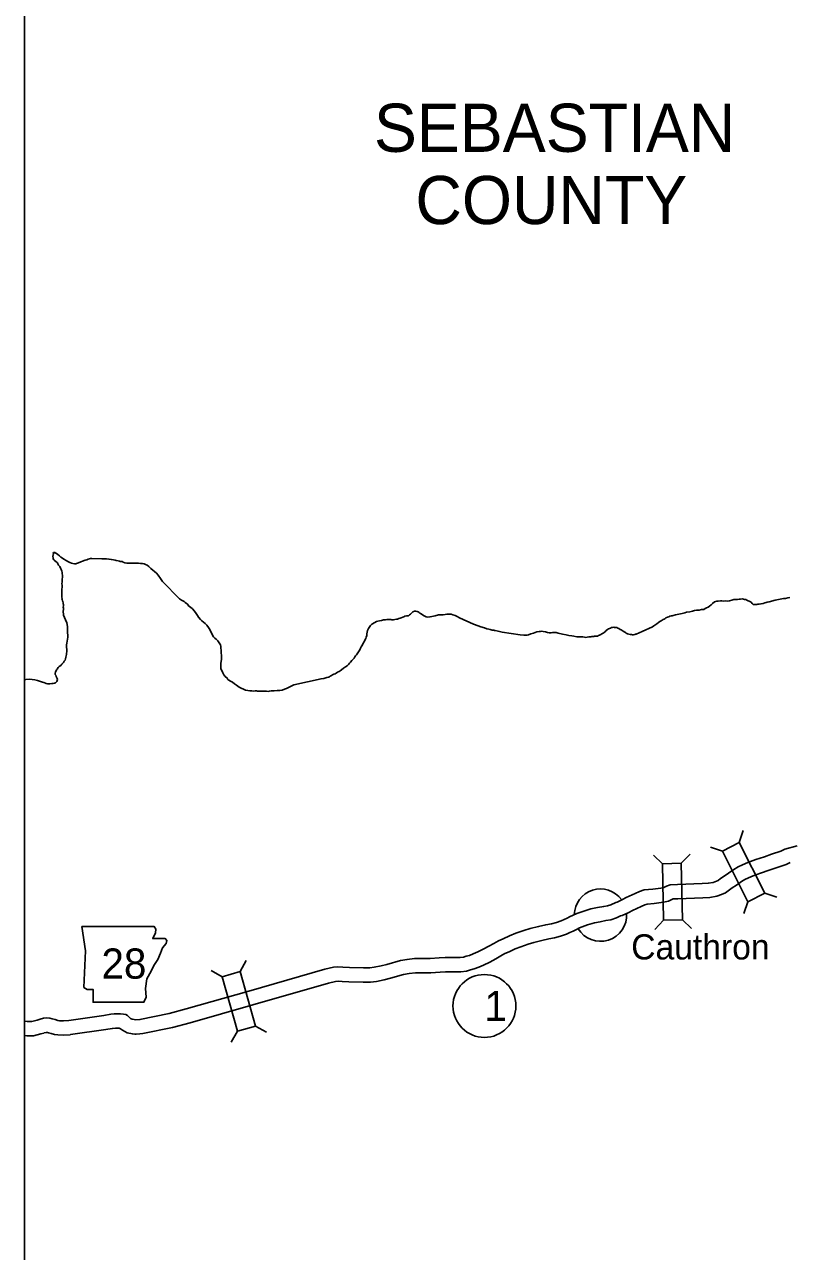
# Model space of a CAD drawing. Extents: x 1382482 to 1385815, y 1168351 to 1170484.
# Drawn here: x 1382642.2 to 1382802.8, y 1169997.3 to 1170254.7 of the extents above; entities that cross this region are included whole.
import ezdxf

# ---------------------------------------------------------------- set-up
doc = ezdxf.new("R2010")
doc.units = 0
for name, color, linetype in [('10', 7, 'Continuous'), ('2', 7, 'Continuous'), ('20', 7, 'Continuous'), ('21', 7, 'Continuous'), ('24', 7, 'Continuous'), ('Default', 7, 'Continuous'), ('R_No Plot', 7, 'Continuous')]:
    doc.layers.add(name, color=color, linetype=linetype)

msp = doc.modelspace()

# ---------------------------------------------------------------- linework, layer by layer
at = {"layer": '10'}
for points in [[(1382804.4, 1170082.41), (1382801.83, 1170081.72), (1382800.95, 1170081.28), (1382798.98, 1170080.63), (1382797.53, 1170080.11), (1382795.74, 1170079.52), (1382794.05, 1170078.93), (1382792.91, 1170078.45), (1382792.01, 1170078), (1382791.07, 1170077.46), (1382789.99, 1170076.65), (1382789.05, 1170076.07), (1382788.33, 1170075.52), (1382787.83, 1170075.13), (1382787.43, 1170074.97), (1382786.79, 1170074.74), (1382785.72, 1170074.56), (1382784.45, 1170074.5), (1382779.26, 1170074.28), (1382777.75, 1170074.25), (1382777, 1170073.96), (1382776.38, 1170073.66), (1382775.81, 1170073.53), (1382774.07, 1170073.31), (1382772.3, 1170073.15), (1382771.28, 1170072.81), (1382770.4, 1170072.39), (1382768.51, 1170071.54), (1382767.73, 1170071.14), (1382766.64, 1170070.62), (1382766.3, 1170070.54), (1382765.3, 1170070.05), (1382764.59, 1170069.8), (1382763.79, 1170069.71), (1382762.45, 1170069.44), (1382761.1, 1170069.19), (1382759.44, 1170068.65), (1382758.18, 1170068.24), (1382757.38, 1170067.88), (1382756.63, 1170067.49), (1382756.14, 1170067.2), (1382755.48, 1170066.96), (1382754.87, 1170066.67), (1382753.88, 1170066.33), (1382752.81, 1170066.07), (1382751.64, 1170065.85), (1382750.12, 1170065.47), (1382748.37, 1170065.05), (1382747.03, 1170064.64), (1382745.34, 1170064.05), (1382743.99, 1170063.54), (1382742.69, 1170062.91), (1382741.73, 1170062.49), (1382740.73, 1170061.92), (1382739.71, 1170061.34), (1382738.52, 1170060.7), (1382737.35, 1170060.15), (1382736.4, 1170059.75), (1382735.61, 1170059.42), (1382734.95, 1170059.23), (1382734.37, 1170059.05), (1382733.65, 1170058.96), (1382730.49, 1170058.99), (1382729.22, 1170058.92), (1382727.38, 1170058.76), (1382724.09, 1170058.78), (1382722.53, 1170058.59), (1382721.11, 1170058.35), (1382718.3, 1170057.53), (1382717.07, 1170057.24), (1382715.61, 1170056.92), (1382714.67, 1170056.8), (1382713.36, 1170056.8), (1382710.42, 1170056.87), (1382709.01, 1170056.97), (1382707.95, 1170057), (1382707.05, 1170056.92), (1382705.29, 1170056.5), (1382689.34, 1170051.92), (1382676.18, 1170048.2), (1382672.6, 1170047.23), (1382666.43, 1170045.97), (1382665.61, 1170045.91)], [(1382802.89, 1170078.9), (1382802.1, 1170078.5), (1382799.96, 1170077.8), (1382798.51, 1170077.27), (1382796.71, 1170076.68), (1382795.13, 1170076.12), (1382794.16, 1170075.72), (1382793.44, 1170075.36), (1382792.72, 1170074.94), (1382791.67, 1170074.17), (1382790.75, 1170073.6), (1382790.16, 1170073.15), (1382789.36, 1170072.52), (1382788.52, 1170072.17), (1382787.55, 1170071.82), (1382786.04, 1170071.57), (1382784.58, 1170071.51), (1382779.36, 1170071.29), (1382778.34, 1170071.26), (1382778.21, 1170071.21), (1382777.39, 1170070.8), (1382776.33, 1170070.57), (1382774.4, 1170070.32), (1382772.92, 1170070.19), (1382772.39, 1170070.01), (1382771.65, 1170069.67), (1382769.81, 1170068.83), (1382769.05, 1170068.45), (1382767.65, 1170067.78), (1382767.33, 1170067.7), (1382766.47, 1170067.28), (1382765.26, 1170066.85), (1382764.25, 1170066.74), (1382763.02, 1170066.49), (1382761.84, 1170066.27), (1382760.37, 1170065.8), (1382759.27, 1170065.43), (1382758.69, 1170065.18), (1382758.07, 1170064.85), (1382757.4, 1170064.47), (1382756.65, 1170064.2), (1382756.01, 1170063.89), (1382754.73, 1170063.45), (1382753.44, 1170063.14), (1382752.28, 1170062.92), (1382750.83, 1170062.55), (1382749.15, 1170062.16), (1382747.96, 1170061.79), (1382746.36, 1170061.23), (1382745.18, 1170060.78), (1382743.94, 1170060.18), (1382743.07, 1170059.8), (1382742.21, 1170059.32), (1382741.17, 1170058.72), (1382739.87, 1170058.02), (1382738.57, 1170057.4), (1382737.55, 1170056.98), (1382736.61, 1170056.59), (1382735.82, 1170056.36), (1382734.98, 1170056.1), (1382733.81, 1170055.96), (1382730.56, 1170055.99), (1382729.44, 1170055.93), (1382727.5, 1170055.76), (1382724.26, 1170055.78), (1382722.96, 1170055.62), (1382721.78, 1170055.42), (1382719.07, 1170054.63), (1382717.74, 1170054.31), (1382716.11, 1170053.96), (1382714.86, 1170053.8), (1382713.32, 1170053.8), (1382710.28, 1170053.87), (1382708.87, 1170053.97), (1382708.04, 1170053.99), (1382707.53, 1170053.95), (1382706.05, 1170053.6), (1382690.16, 1170049.04), (1382676.98, 1170045.31), (1382673.3, 1170044.31), (1382667.09, 1170043.05)], [(1382660.33, 1170047.07), (1382658.86, 1170046.82), (1382651.5, 1170045.78)], [(1382660.33, 1170047.07), (1382661.05, 1170047.16), (1382661.68, 1170047.19), (1382662.35, 1170047.19), (1382662.97, 1170047.12), (1382663.49, 1170046.99), (1382663.83, 1170046.78), (1382664.14, 1170046.51), (1382664.49, 1170046.21), (1382664.83, 1170046.02), (1382665.27, 1170045.94), (1382665.61, 1170045.91)], [(1382645.48, 1170046.03), (1382644.85, 1170045.82), (1382643.77, 1170045.56), (1382642.79, 1170045.58), (1382642.23, 1170045.59)], [(1382645.48, 1170046.03), (1382646.19, 1170046.24), (1382646.8, 1170046.3), (1382647.51, 1170046.24), (1382648.03, 1170046.12), (1382648.65, 1170045.95), (1382649.2, 1170045.78), (1382649.59, 1170045.72), (1382650.39, 1170045.67), (1382651.5, 1170045.78)], [(1382646.26, 1170043.13), (1382645.68, 1170042.94), (1382644.1, 1170042.55), (1382642.72, 1170042.58), (1382642.23, 1170042.59)], [(1382646.32, 1170043.15), (1382646.78, 1170043.28), (1382646.82, 1170043.28), (1382647.05, 1170043.26), (1382647.29, 1170043.21), (1382647.81, 1170043.06), (1382648.53, 1170042.85), (1382649.25, 1170042.73), (1382650.44, 1170042.66), (1382651.79, 1170042.79)], [(1382660.59, 1170044.07), (1382659.32, 1170043.86), (1382651.85, 1170042.8)], [(1382660.69, 1170044.08), (1382660.59, 1170044.07)], [(1382660.69, 1170044.08), (1382661.31, 1170044.16)], [(1382661.31, 1170044.16), (1382661.73, 1170044.18), (1382662.06, 1170044.13), (1382662.37, 1170043.99), (1382662.78, 1170043.73)], [(1382662.78, 1170043.73), (1382663.78, 1170043.15), (1382664.87, 1170042.95), (1382665.35, 1170042.91)], [(1382665.35, 1170042.91), (1382665.69, 1170042.9), (1382666.41, 1170042.98), (1382667.09, 1170043.05)]]:
    msp.add_lwpolyline(points, dxfattribs=at)
at = {"layer": '2'}
for points in [[(1382647.53, 1170116.39), (1382647.95, 1170116.44), (1382648.25, 1170116.46), (1382648.52, 1170116.52), (1382648.72, 1170116.63), (1382648.88, 1170116.75), (1382648.99, 1170116.88), (1382649.08, 1170117.06), (1382649.12, 1170117.32), (1382649.09, 1170117.51), (1382648.96, 1170117.77), (1382648.88, 1170117.9), (1382648.78, 1170118.22), (1382648.69, 1170118.37), (1382648.67, 1170118.56), (1382648.72, 1170118.89), (1382648.84, 1170119.13), (1382648.94, 1170119.3), (1382649.09, 1170119.49), (1382649.3, 1170119.8), (1382649.52, 1170120.02), (1382649.82, 1170120.25), (1382650.07, 1170120.5), (1382650.27, 1170120.7), (1382650.39, 1170120.86), (1382650.58, 1170121.13), (1382650.73, 1170121.36), (1382650.83, 1170121.66), (1382650.91, 1170121.95), (1382650.99, 1170122.23), (1382651.04, 1170122.52), (1382651.07, 1170122.81), (1382651.11, 1170123.1), (1382651.1, 1170123.62), (1382651.03, 1170124.1), (1382651.07, 1170124.54), (1382651.08, 1170124.9), (1382651.17, 1170125.32), (1382651.25, 1170125.76), (1382651.29, 1170126.16), (1382651.3, 1170126.63), (1382651.28, 1170127.12), (1382651.28, 1170127.39), (1382651.25, 1170127.87), (1382651.23, 1170128.33), (1382651.19, 1170128.83), (1382651.13, 1170129.16), (1382650.85, 1170129.83), (1382650.62, 1170130.32), (1382650.44, 1170130.79), (1382650.38, 1170131.09), (1382650.33, 1170131.39), (1382650.37, 1170131.63), (1382650.38, 1170132.01), (1382650.38, 1170132.27), (1382650.34, 1170132.5), (1382650.38, 1170132.76), (1382650.38, 1170133.02), (1382650.36, 1170133.16), (1382650.32, 1170133.4), (1382650.26, 1170133.63), (1382650.21, 1170133.82), (1382650.11, 1170134.07), (1382650.09, 1170134.23), (1382650.1, 1170134.41), (1382650.09, 1170134.55), (1382650.09, 1170134.75), (1382650.08, 1170134.94), (1382650.06, 1170135.27), (1382650.05, 1170135.48), (1382650.07, 1170135.78), (1382650.06, 1170136.15), (1382650.1, 1170136.74), (1382650.1, 1170137.03), (1382650.09, 1170137.46), (1382650.12, 1170137.73), (1382650.13, 1170137.94), (1382650.14, 1170138.2), (1382650.15, 1170138.43), (1382650.18, 1170138.71), (1382650.22, 1170138.98), (1382650.18, 1170139.2), (1382650.13, 1170139.48), (1382650.11, 1170139.77), (1382650.07, 1170140.03), (1382649.99, 1170140.22), (1382649.86, 1170140.5), (1382649.61, 1170140.97), (1382649.39, 1170141.3), (1382649.23, 1170141.57), (1382649.12, 1170141.75), (1382648.8, 1170142.04), (1382648.53, 1170142.26), (1382648.39, 1170142.43), (1382648.24, 1170142.64), (1382648.21, 1170142.81), (1382648.2, 1170143.1), (1382648.26, 1170143.42), (1382648.28, 1170143.61), (1382648.27, 1170143.78), (1382648.31, 1170143.92)], [(1382648.31, 1170143.92), (1382648.38, 1170143.97), (1382648.5, 1170143.97), (1382648.6, 1170143.94), (1382648.69, 1170143.9), (1382648.92, 1170143.73), (1382649.24, 1170143.49), (1382649.58, 1170143.21), (1382649.88, 1170142.99), (1382650.17, 1170142.76), (1382650.51, 1170142.54), (1382650.96, 1170142.25), (1382651.35, 1170142.03), (1382651.71, 1170141.85), (1382652.12, 1170141.7), (1382652.4, 1170141.6), (1382652.75, 1170141.56), (1382653.02, 1170141.55), (1382653.17, 1170141.61), (1382653.58, 1170141.77), (1382654.04, 1170141.97), (1382654.41, 1170142.15), (1382654.98, 1170142.35), (1382655.29, 1170142.42), (1382655.59, 1170142.57), (1382656.06, 1170142.65), (1382656.36, 1170142.69), (1382658.48, 1170142.64), (1382659.09, 1170142.62), (1382659.44, 1170142.61), (1382659.95, 1170142.55), (1382660.45, 1170142.45), (1382660.88, 1170142.4), (1382661.22, 1170142.33), (1382661.46, 1170142.25), (1382661.88, 1170142.18), (1382662.13, 1170142.1), (1382662.32, 1170142.08), (1382662.53, 1170142.06), (1382662.73, 1170142.06), (1382662.9, 1170141.89), (1382663.25, 1170141.76), (1382663.7, 1170141.72), (1382664.56, 1170141.7), (1382665.51, 1170141.73), (1382666.13, 1170141.7), (1382666.57, 1170141.63), (1382666.98, 1170141.62), (1382667.33, 1170141.55), (1382667.64, 1170141.44), (1382667.95, 1170141.27), (1382668.34, 1170140.98), (1382668.77, 1170140.61), (1382669.19, 1170140.2), (1382669.52, 1170139.95), (1382669.94, 1170139.59), (1382670.27, 1170139.15), (1382670.77, 1170138.47), (1382671.22, 1170137.84), (1382674.73, 1170134.2), (1382675.16, 1170133.96), (1382675.72, 1170133.65), (1382675.97, 1170133.47), (1382676.4, 1170133.12), (1382676.74, 1170132.71), (1382677.04, 1170132.48), (1382677.48, 1170132.09), (1382677.89, 1170131.62), (1382678.23, 1170131.15), (1382678.54, 1170130.7), (1382678.76, 1170130.36), (1382679.13, 1170129.9), (1382679.45, 1170129.63), (1382679.77, 1170129.35), (1382680.16, 1170129.04), (1382680.5, 1170128.66), (1382680.85, 1170128.2), (1382681.09, 1170127.78), (1382681.36, 1170127.33), (1382681.53, 1170126.97), (1382681.73, 1170126.49), (1382681.89, 1170126.28), (1382682.2, 1170125.96), (1382682.43, 1170125.75), (1382682.78, 1170125.43), (1382683.09, 1170125), (1382683.37, 1170124.56), (1382683.44, 1170124.19), (1382683.44, 1170123.86), (1382683.47, 1170123.42), (1382683.48, 1170122.91), (1382683.55, 1170122.35), (1382683.55, 1170121.99), (1382683.55, 1170121.57), (1382683.5, 1170121.08), (1382683.45, 1170120.7), (1382683.41, 1170120.3), (1382683.42, 1170119.95), (1382683.44, 1170119.52), (1382683.68, 1170119.03), (1382683.87, 1170118.68)], [(1382784.78, 1170132), (1382785.08, 1170132.2), (1382785.36, 1170132.34), (1382785.7, 1170132.5), (1382785.99, 1170132.68), (1382786.36, 1170132.98), (1382786.59, 1170133.22), (1382787.03, 1170133.57), (1382787.53, 1170133.72), (1382787.83, 1170133.73), (1382788.29, 1170133.78), (1382788.57, 1170133.79), (1382788.99, 1170133.76), (1382789.36, 1170133.77), (1382789.73, 1170133.76), (1382790.2, 1170133.82), (1382790.68, 1170133.95), (1382791.09, 1170134.05), (1382791.5, 1170134.07), (1382791.88, 1170134.09), (1382792.2, 1170134.13), (1382792.53, 1170134.18), (1382792.92, 1170134.2), (1382793.32, 1170134.09), (1382793.65, 1170134.05), (1382793.86, 1170133.96), (1382794.12, 1170133.82), (1382794.34, 1170133.7), (1382794.71, 1170133.53), (1382794.95, 1170133.26), (1382795.17, 1170133.04), (1382795.42, 1170133.02), (1382795.7, 1170133.03), (1382795.92, 1170133.05), (1382796.14, 1170133.08), (1382796.41, 1170133.1), (1382796.78, 1170133.14), (1382797.26, 1170133.22), (1382797.62, 1170133.37), (1382797.91, 1170133.46), (1382798.12, 1170133.52), (1382798.49, 1170133.62), (1382799.79, 1170133.95), (1382800.48, 1170134.09), (1382801.49, 1170134.26), (1382801.96, 1170134.31), (1382802.41, 1170134.4), (1382802.82, 1170134.49)], [(1382762.7, 1170126.53), (1382762.88, 1170126.61), (1382763.2, 1170126.75), (1382763.41, 1170126.85), (1382763.64, 1170126.99), (1382763.88, 1170127.14), (1382763.96, 1170127.21), (1382764.1, 1170127.32), (1382764.25, 1170127.52), (1382764.33, 1170127.57), (1382764.61, 1170127.75), (1382764.79, 1170127.9), (1382765, 1170128.01), (1382765.21, 1170128.08), (1382765.43, 1170128.19), (1382765.61, 1170128.23), (1382765.88, 1170128.24), (1382766.08, 1170128.22), (1382766.29, 1170128.21), (1382766.51, 1170128.19), (1382766.74, 1170128.09), (1382766.96, 1170127.98), (1382767.27, 1170127.78), (1382767.45, 1170127.69), (1382767.9, 1170127.41), (1382768.2, 1170127.23), (1382768.34, 1170127.17), (1382768.53, 1170127.04), (1382768.81, 1170126.9), (1382769.07, 1170126.8), (1382769.31, 1170126.75), (1382769.59, 1170126.71), (1382769.82, 1170126.7), (1382770.04, 1170126.69), (1382770.29, 1170126.73), (1382770.43, 1170126.78), (1382770.61, 1170126.81), (1382771.2, 1170127.06), (1382771.88, 1170127.37), (1382774.01, 1170128.33), (1382774.31, 1170128.53), (1382774.54, 1170128.7), (1382774.7, 1170128.82), (1382774.95, 1170129), (1382775.28, 1170129.25), (1382775.59, 1170129.43), (1382775.83, 1170129.58), (1382776.05, 1170129.71), (1382776.3, 1170129.86), (1382776.45, 1170129.97), (1382776.59, 1170130.05), (1382776.84, 1170130.21), (1382777.15, 1170130.36), (1382777.44, 1170130.47), (1382777.7, 1170130.55), (1382777.95, 1170130.62), (1382778.14, 1170130.67), (1382778.37, 1170130.72), (1382778.86, 1170130.87), (1382780.26, 1170131.16), (1382780.81, 1170131.29), (1382781.19, 1170131.39), (1382781.84, 1170131.51), (1382782.42, 1170131.63), (1382782.85, 1170131.76), (1382783.26, 1170131.81), (1382783.83, 1170131.87), (1382784.32, 1170131.95), (1382784.76, 1170131.99)], [(1382784.76, 1170131.99), (1382784.78, 1170132)], [(1382683.87, 1170118.68), (1382684.09, 1170118.31), (1382684.35, 1170117.94), (1382684.76, 1170117.59), (1382684.93, 1170117.32), (1382685.14, 1170117.14), (1382685.44, 1170116.97), (1382685.9, 1170116.71), (1382686.32, 1170116.41), (1382686.73, 1170116.13), (1382687.28, 1170115.72), (1382687.69, 1170115.48), (1382688.18, 1170115.25), (1382688.6, 1170115.08), (1382689.12, 1170114.99), (1382689.55, 1170114.93), (1382689.94, 1170114.89), (1382690.29, 1170114.88), (1382690.63, 1170114.91), (1382690.91, 1170114.9), (1382691.09, 1170114.87), (1382691.51, 1170114.87), (1382691.97, 1170114.84), (1382692.26, 1170114.82), (1382692.61, 1170114.85), (1382692.98, 1170114.86), (1382693.36, 1170114.81), (1382693.62, 1170114.87), (1382693.98, 1170114.91), (1382694.3, 1170114.91), (1382694.63, 1170114.91), (1382695.22, 1170114.96), (1382695.79, 1170115.02), (1382696.28, 1170115.08), (1382696.78, 1170115.25), (1382697.19, 1170115.41), (1382697.52, 1170115.58), (1382697.93, 1170115.76), (1382698.18, 1170115.91), (1382698.47, 1170116.05), (1382698.77, 1170116.16), (1382704.46, 1170117.45), (1382705.07, 1170117.53), (1382705.68, 1170117.71), (1382706, 1170117.77), (1382706.22, 1170117.87), (1382706.39, 1170117.99), (1382706.67, 1170118.17), (1382706.87, 1170118.29), (1382707.12, 1170118.39), (1382707.42, 1170118.51), (1382707.66, 1170118.63), (1382707.91, 1170118.81), (1382708.23, 1170118.97), (1382708.46, 1170119.11), (1382708.74, 1170119.32), (1382709.19, 1170119.66), (1382709.61, 1170119.92), (1382709.95, 1170120.18), (1382710.21, 1170120.46), (1382710.46, 1170120.73), (1382710.65, 1170120.94), (1382710.92, 1170121.25), (1382711.2, 1170121.55), (1382711.39, 1170121.8), (1382711.56, 1170122.04), (1382711.72, 1170122.23), (1382711.91, 1170122.49), (1382712.16, 1170122.88), (1382712.46, 1170123.28), (1382712.6, 1170123.55), (1382712.74, 1170123.86), (1382712.91, 1170124.17), (1382713.14, 1170124.56), (1382713.33, 1170124.92), (1382713.5, 1170125.23), (1382713.67, 1170125.56), (1382713.83, 1170125.91), (1382713.95, 1170126.19), (1382714.04, 1170126.55), (1382714.05, 1170126.9), (1382714.13, 1170127.21), (1382714.23, 1170127.54), (1382714.31, 1170127.73), (1382714.42, 1170127.96), (1382714.56, 1170128.2), (1382714.67, 1170128.42), (1382714.84, 1170128.65), (1382715.09, 1170128.92), (1382715.72, 1170129.28), (1382716.1, 1170129.43), (1382716.4, 1170129.51), (1382716.71, 1170129.59), (1382717.12, 1170129.65), (1382717.6, 1170129.82), (1382717.97, 1170129.84), (1382718.27, 1170129.86), (1382718.66, 1170129.86), (1382719.09, 1170129.86), (1382719.35, 1170129.83), (1382719.69, 1170129.84)], [(1382719.69, 1170129.84), (1382719.96, 1170129.87), (1382720.3, 1170129.92), (1382720.53, 1170129.98), (1382720.81, 1170130.06), (1382721.06, 1170130.19), (1382721.83, 1170130.47), (1382722.05, 1170130.57), (1382722.41, 1170130.66), (1382722.8, 1170130.68), (1382723.04, 1170130.83), (1382723.25, 1170130.98), (1382723.44, 1170131.22), (1382723.72, 1170131.48), (1382724.1, 1170131.6), (1382724.39, 1170131.61), (1382724.62, 1170131.58), (1382724.85, 1170131.46), (1382725.03, 1170131.34), (1382725.23, 1170131.22), (1382725.49, 1170131.05), (1382725.96, 1170130.74), (1382726.38, 1170130.53), (1382726.25, 1170130.6), (1382726.54, 1170130.46), (1382726.9, 1170130.37), (1382727.3, 1170130.42), (1382727.69, 1170130.49), (1382728.41, 1170130.68), (1382729.08, 1170130.83), (1382729.67, 1170130.88), (1382730.11, 1170130.89), (1382730.53, 1170130.94), (1382730.86, 1170130.97), (1382731.31, 1170130.99), (1382731.75, 1170130.97), (1382732.13, 1170130.88), (1382732.62, 1170130.72), (1382733.01, 1170130.54), (1382733.54, 1170130.23), (1382736.45, 1170128.91), (1382737.46, 1170128.58), (1382737.98, 1170128.37), (1382738.74, 1170128.12), (1382739.25, 1170127.95), (1382739.67, 1170127.84), (1382739.96, 1170127.76), (1382740.19, 1170127.69), (1382740.37, 1170127.67), (1382740.56, 1170127.64), (1382740.71, 1170127.62), (1382740.87, 1170127.58), (1382741.02, 1170127.56), (1382741.62, 1170127.43), (1382742.49, 1170127.25), (1382746.27, 1170126.68), (1382747.01, 1170126.57), (1382747.38, 1170126.61), (1382747.72, 1170126.63), (1382748.02, 1170126.7), (1382748.51, 1170126.88), (1382749.04, 1170127.03), (1382749.4, 1170127.17), (1382749.76, 1170127.27), (1382750.23, 1170127.34), (1382750.54, 1170127.4), (1382750.8, 1170127.44), (1382751.06, 1170127.39), (1382751.55, 1170127.27), (1382751.99, 1170127.16), (1382752.32, 1170127.12), (1382752.78, 1170127.12), (1382753.03, 1170127.15), (1382753.3, 1170127.18), (1382753.61, 1170127.19), (1382753.84, 1170127.16), (1382754.22, 1170127.04), (1382755.17, 1170126.78), (1382755.92, 1170126.65), (1382756.5, 1170126.54), (1382757.07, 1170126.48), (1382757.52, 1170126.39), (1382758.18, 1170126.28), (1382758.59, 1170126.27), (1382758.93, 1170126.26), (1382759.44, 1170126.23), (1382759.75, 1170126.19), (1382760.03, 1170126.14), (1382760.33, 1170126.18), (1382760.65, 1170126.23), (1382760.92, 1170126.27), (1382761.08, 1170126.28), (1382761.29, 1170126.32), (1382761.68, 1170126.35), (1382761.82, 1170126.37), (1382761.96, 1170126.37), (1382762.09, 1170126.37), (1382762.21, 1170126.38), (1382762.41, 1170126.4), (1382762.51, 1170126.41), (1382762.7, 1170126.53)], [(1382647.53, 1170116.39), (1382647.23, 1170116.39), (1382647.04, 1170116.42), (1382646.8, 1170116.44), (1382646.6, 1170116.53), (1382646.27, 1170116.65), (1382645.98, 1170116.72), (1382644.96, 1170117.07), (1382644.38, 1170117.2), (1382643.82, 1170117.3), (1382643.3, 1170117.36), (1382642.52, 1170117.27), (1382642.23, 1170117.23)]]:
    msp.add_lwpolyline(points, dxfattribs=at)
at = {"layer": '20'}
for p, q in [((1382792.23, 1170083.08), (1382793.05, 1170085.59)), ((1382776.11, 1170078.66), (1382774.21, 1170080.48)), ((1382780.07, 1170078.74), (1382781.9, 1170080.65)), ((1382788.69, 1170081.3), (1382786.18, 1170082.12)), ((1382794.05, 1170070.69), (1382793.23, 1170068.19)), ((1382797.59, 1170072.48), (1382800.09, 1170071.66)), ((1382776.37, 1170066.78), (1382774.54, 1170064.87)), ((1382780.33, 1170066.87), (1382782.24, 1170065.04)), ((1382687.49, 1170056.01), (1382688.78, 1170058.32)), ((1382683.68, 1170054.94), (1382681.38, 1170056.23)), ((1382690.72, 1170044.58), (1382693.03, 1170043.29)), ((1382686.91, 1170043.51), (1382685.62, 1170041.2))]:
    msp.add_line(p, q, dxfattribs=at)
for points in [[(1382797.59, 1170072.48), (1382792.23, 1170083.08), (1382788.69, 1170081.3), (1382794.05, 1170070.69)], [(1382780.33, 1170066.87), (1382780.07, 1170078.74), (1382776.11, 1170078.66), (1382776.37, 1170066.78)], [(1382683.68, 1170054.94), (1382686.91, 1170043.51), (1382690.72, 1170044.58), (1382687.49, 1170056.01)]]:
    msp.add_lwpolyline(points, close=True, dxfattribs=at)
at = {"layer": '21'}
msp.add_lwpolyline([(1382654.25, 1170065.48), (1382655.02, 1170060.41), (1382654.68, 1170052.71), (1382655.35, 1170052.29), (1382656.62, 1170052.29), (1382656.62, 1170049.58), (1382667.28, 1170049.58), (1382667.79, 1170050.68), (1382667.62, 1170052.46), (1382667.87, 1170054.49), (1382668.8, 1170056.09), (1382669.4, 1170057.28), (1382670.24, 1170058.55), (1382670.75, 1170059.9), (1382671.17, 1170061), (1382671.93, 1170061.93), (1382672.1, 1170062.52), (1382671.76, 1170062.95), (1382669.14, 1170062.95), (1382669.73, 1170064.13), (1382669.82, 1170064.89), (1382669.47, 1170065.48)], close=True, dxfattribs=at)
at = {"layer": '24'}
for start, end in [(36.6604, 178.8086), (211.1653, 3.8004)]:
    msp.add_arc((1382763.11, 1170067.87), 5.5, start, end, dxfattribs=at)
at = {"layer": 'Default'}
msp.add_circle((1382738.75, 1170048.81), 6.6, dxfattribs=at)
at = {"layer": 'R_No Plot'}
msp.add_lwpolyline([(1382642.23, 1170388.77), (1383371.62, 1170388.77), (1383371.62, 1169604.28), (1382642.23, 1169604.28)], close=True, dxfattribs=at)

# ---------------------------------------------------------------- texts
at = {"layer": '21'}
msp.add_text('28', height=6.336, dxfattribs=at).set_placement((1382658.38, 1170054.54))
at = {"layer": '24'}
msp.add_text('Cauthron', height=5.28, dxfattribs=at).set_placement((1382769.56, 1170058.57))
at = {"layer": 'Default'}
for s, p in [('SEBASTIAN', (1382715.56, 1170227.98)), ('COUNTY', (1382724.26, 1170212.82))]:
    msp.add_text(s, height=10.107, rotation=360, dxfattribs=at).set_placement(p)
msp.add_text('1', height=6.34, dxfattribs=at).set_placement((1382738.75, 1170045.64))

doc.saveas('drawing.dxf')
